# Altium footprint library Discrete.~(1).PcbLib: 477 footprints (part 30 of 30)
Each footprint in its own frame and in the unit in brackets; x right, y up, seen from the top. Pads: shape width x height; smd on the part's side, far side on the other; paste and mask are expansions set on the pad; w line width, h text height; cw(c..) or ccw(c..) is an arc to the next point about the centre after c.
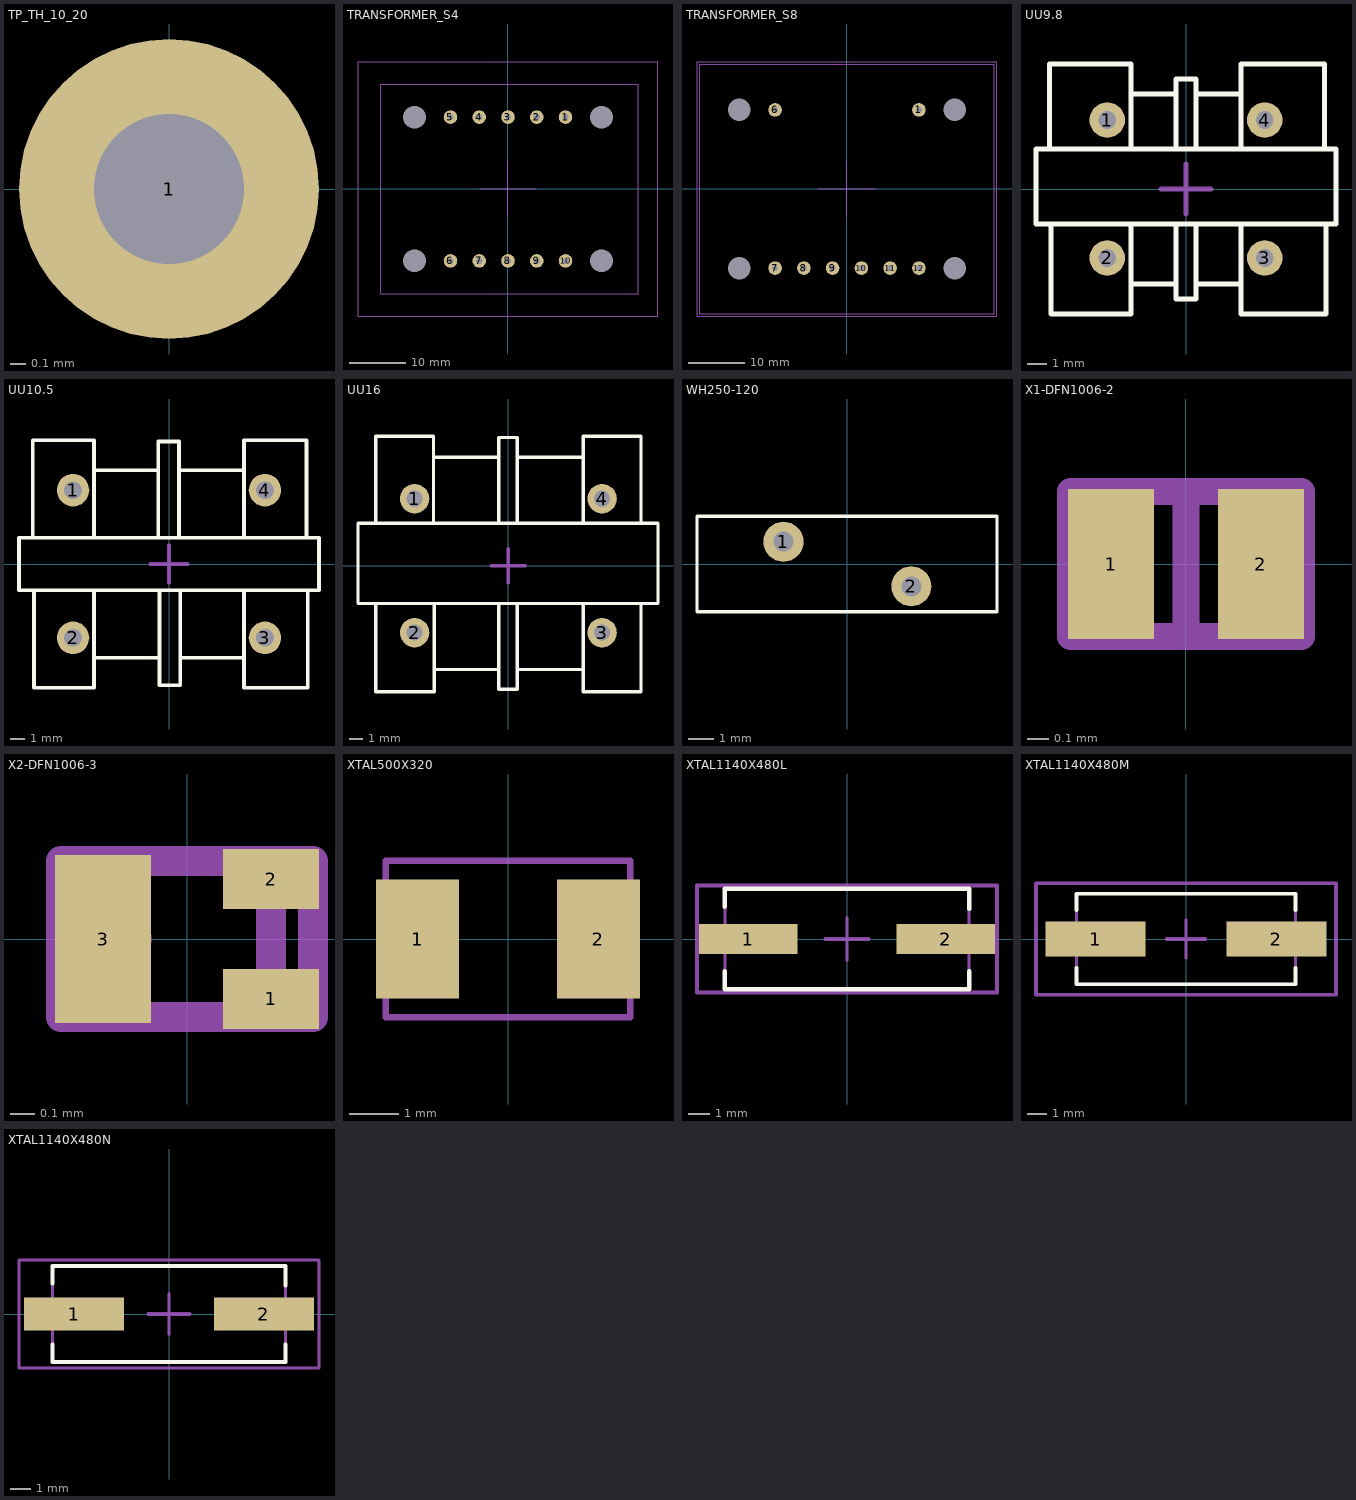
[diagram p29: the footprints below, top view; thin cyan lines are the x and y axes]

## TP_TH_10_20 [mm]
pads (1):
  round 2 hole 1: 1(0,0)

## TRANSFORMER_S4 [mm]
pads (14):
  round 2.4 hole 1.1: 1(10.16,12.7) 2(5.08,12.7) 3(0,12.7) 4(-5.08,12.7) 5(-10.16,12.7) 6(-10.16,-12.7) 7(-5.08,-12.7) 8(0,-12.7) 9(5.08,-12.7) 10(10.16,-12.7)
  round 1 hole 4: MH(-16.51,-12.7) MH(-16.51,12.7) MH(16.51,-12.7) MH(16.51,12.7)
Mechanical 1:
  lines w0.1: -22.5,-18.5 -22.5,18.5 23,18.5 23,-18.5 -22.5,-18.5
Mechanical 15:
  lines w0.1: -5,0 5,0 ; 0,-5 0,5 ; -26.5,-22.5 -26.5,22.5 26.5,22.5 26.5,-22.5 -26.5,-22.5
3D body: height 38, standoff 31, extent -18,-12.5 18,12.5
3D body: height 31, standoff 1, extent -22.5,-18.5 23,18.5

## TRANSFORMER_S8 [mm]
pads (12):
  round 2.4 hole 1.1: 1(12.7,13.97) 6(-12.7,13.97) 7(-12.7,-13.97) 8(-7.62,-13.97) 9(-2.54,-13.97) 10(2.54,-13.97) 11(7.62,-13.97) 12(12.7,-13.97)
  round 1 hole 4: MH(-19.05,-13.97) MH(-19.05,13.97) MH(19.05,-13.97) MH(19.05,13.97)
Mechanical 1:
  lines w0.1: -26,-22 26,-22 26,22 -26,22 -26,-22
Mechanical 15:
  lines w0.1: -5,0 5,0 ; 0,-5 0,5 ; -26.5,-22.5 26.5,-22.5 26.5,22.5 -26.5,22.5 -26.5,-22.5
3D body: height 31, standoff 1, extent -26,-22 26,22
3D body: height 38, standoff 31, extent -18,-15 18,15

## UU9.8 [mm] "17*12*17mm(长宽高）"
pads (4):
  round 1.8 hole 0.9: 1(-4,3.5) 2(-4,-3.5) 3(4,-3.5) 4(4,3.5)
Top Overlay:
  lines w0.254: -6.943,2.032 -6.943,6.35 -2.794,6.35 -2.794,2.032 ; -6.858,-1.778 -6.858,-6.35 -2.794,-6.35 -2.794,-1.778 ; -2.794,-4.826 -0.638,-4.826 ; -2.794,4.826 -0.508,4.826 ; -0.508,-1.778 -0.508,-5.588 0.508,-5.588 0.508,-1.778 ; -0.508,2.032 -0.508,5.588 0.508,5.588 0.508,2.032 ; 0.508,-4.826 2.794,-4.826 ; 0.508,4.826 2.794,4.826 ; 2.794,-1.778 2.794,-6.35 7.112,-6.35 7.112,-1.778 ; 2.794,2.032 2.794,6.35 7.027,6.35 7.027,2.032 ; -7.62,-1.778 -7.62,2.032 7.62,2.032 7.62,-1.778 -7.62,-1.778
Mechanical 15:
  lines w0.254: -1.27,0 1.27,0 ; 0,-1.27 0,1.27
3D body "UU9.8.STEP": height 17.05, standoff -3.45, extent -8.5,-6 8.5,6

## UU10.5 [mm] "18*16*20mm(长宽高）"
pads (4):
  round 2.2 hole 1.2: 1(-6.5,5) 2(-6.5,-5) 3(6.5,-5) 4(6.5,5)
Top Overlay:
  lines w0.254: -9.229,1.904 -9.229,8.382 -5.08,8.382 -5.08,1.904 ; -9.144,-1.81 -9.144,-8.382 -5.08,-8.382 -5.08,-1.81 ; -5.08,-6.35 -0.638,-6.35 ; -5.08,6.35 -0.723,6.35 ; -0.723,1.904 -0.723,8.304 0.677,8.304 0.677,1.904 ; -0.638,-1.81 -0.638,-8.21 0.762,-8.21 0.762,-1.81 ; 0.677,6.35 5.08,6.35 ; 0.762,-6.35 5.08,-6.35 ; 5.08,-1.904 5.08,-8.382 9.398,-8.382 9.398,-1.904 ; 5.08,1.904 5.08,8.382 9.313,8.382 9.313,1.904 ; -10.16,-1.778 -10.16,1.778 10.16,1.778 10.16,-1.778 -10.16,-1.778
Mechanical 15:
  lines w0.254: -1.27,0 1.27,0 ; 0,-1.27 0,1.27
3D body "UU10.5.STEP": height 21.05, standoff -3.45, extent -9.4,-8 9.4,8

## UU16 [mm] "22*17.5*23mm(长宽高）"
pads (4):
  round 2.2 hole 1.2: 1(-7,5) 2(-7,-5) 3(7,-5) 4(7,5)
Top Overlay:
  lines w0.254: -9.906,-2.826 -9.906,-9.398 -5.523,-9.398 -5.523,-2.826 ; -9.906,3.174 -9.906,9.652 -5.588,9.652 -5.588,3.174 ; -5.523,-7.749 -0.723,-7.749 ; -5.523,8.097 -0.723,8.097 ; -0.723,-2.826 -0.723,-9.226 0.677,-9.226 0.677,-2.826 ; -0.723,3.174 -0.723,9.574 0.677,9.574 0.677,3.174 ; 0.677,-7.749 5.477,-7.749 ; 0.677,8.097 5.477,8.097 ; 5.588,-2.92 5.588,-9.398 9.906,-9.398 9.906,-2.92 ; 5.588,3.174 5.588,9.652 9.906,9.652 9.906,3.174 ; -11.223,-2.826 11.177,-2.826 11.177,3.174 -11.223,3.174 -11.223,-2.826
Mechanical 15:
  lines w0.254: -1.27,0 1.27,0 ; 0,-1.27 0,1.27
3D body "UU16.STEP": height 22.05, standoff -3.45, extent -11,-8.75 11,8.75

## WH250-120 [mm]
pads (2):
  round 1.6 hole 0.8: 1(-2.55,0.889) 2(2.55,-0.889)
Top Overlay:
  lines w0.127: -6,-1.905 -6,1.905 5.969,1.905 5.969,-1.905 -6,-1.905
3D body "User Library-MF-R250.STEP": height 18.3, standoff -7.6, extent -6,-1.41 6,1.41

## X1-DFN1006-2 [mm]
pads (2):
  rect 0.4x0.7 smd: 1(-0.35,0) 2(0.35,0)
Mechanical 13:
  lines w0.127: -0.375,-0.338 -0.375,0.338 ; 0,-0.338 0,0.338 ; -0.538,-0.338 0.538,-0.338 0.538,0.338 -0.538,0.338 -0.538,-0.338
3D body: height 0.53, standoff 0, extent -0.538,-0.338 0.538,0.338

## X2-DFN1006-3 [mm]
pads (3):
  rect 0.4x0.25 smd: 1(0.35,-0.25) 2(0.35,0.25)
  rect 0.4x0.7 smd: 3(-0.35,0)
Mechanical 13:
  lines w0.127: 0.35,-0.25 0.35,0.25 ; -0.525,-0.325 -0.525,0.325 0.525,0.325 0.525,-0.325 -0.525,-0.325
  lines w0.254: -0.277,0.028 ccw(c-0.285,0.014) -0.275,0
3D body: height 0.4, standoff 0, extent -0.525,-0.325 0.525,0.325

## XTAL500X320 [mm]
pads (2):
  rect 1.7x2.44 smd: 1(-1.85,0) 2(1.85,0)
Mechanical 13:
  lines w0.127: -2.5,-1.6 2.5,-1.6 2.5,1.6 -2.5,1.6 -2.5,-1.6
3D body "User Library-ABM3-1.STEP": height 1.3, standoff 0, extent -2.5,-1.6 2.5,1.6

## XTAL1140X480L [mm] "SMD Crystal"
height 4
pads (2):
  rect 4.6x1.4 smd: 1(-4.6,0) 2(4.6,0)
Top Overlay:
  lines w0.2: -5.7,-1.5 -5.7,-2.35 5.7,-2.35 5.7,-1.5 ; -5.7,1.5 -5.7,2.35 5.7,2.35 5.7,1.4
Mechanical 13:
  lines w0.15: -5.7,-2.35 -5.7,2.35 5.7,2.35 5.7,-2.35 -5.7,-2.35
Mechanical 15:
  lines w0.15: 0,-1 0,1
  lines w0.2: -1,0 1,0 ; -7,-2.5 -7,2.5 7,2.5 7,-2.5 -7,-2.5
3D body "User Library-Crystal HC49_US-SM.STEP": height 4.3, standoff 0, extent -6.4,-2.415 6.4,2.415

## XTAL1140X480M [mm] "SMD Crystal"
height 4
pads (2):
  rect 5.2x1.8 smd: 1(-4.7,0) 2(4.7,0)
Top Overlay:
  lines w0.2: -5.7,-1.5 -5.7,-2.35 5.7,-2.35 5.7,-1.5 ; -5.7,1.5 -5.7,2.35 5.7,2.35 5.7,1.5
Mechanical 13:
  lines w0.15: -5.7,-2.35 5.7,-2.35 5.7,2.35 -5.7,2.35 -5.7,-2.35
Mechanical 15:
  lines w0.15: 0,-1 0,1
  lines w0.2: -1,0 1,0 ; -7.8,-2.9 7.8,-2.9 7.8,2.9 -7.8,2.9 -7.8,-2.9
3D body "User Library-Crystal HC49_US-SM.STEP": height 4.3, standoff 0, extent -6.4,-2.415 6.4,2.415

## XTAL1140X480N [mm] "SMD Crystal"
height 4
pads (2):
  rect 4.9x1.6 smd: 1(-4.65,0) 2(4.65,0)
Top Overlay:
  lines w0.2: -5.7,-1.5 -5.7,-2.35 5.7,-2.35 5.7,-1.5 ; -5.7,1.5 -5.7,2.35 5.7,2.35 5.7,1.4
Mechanical 13:
  lines w0.15: -5.7,-2.35 5.7,-2.35 5.7,2.35 -5.7,2.35 -5.7,-2.35
Mechanical 15:
  lines w0.15: 0,-1 0,1 ; -7.35,-2.65 7.35,-2.65 7.35,2.65 -7.35,2.65 -7.35,-2.65
  lines w0.2: -1,0 1,0
3D body "User Library-Crystal HC49_US-SM.STEP": height 4.3, standoff 0, extent -6.4,-2.415 6.4,2.415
